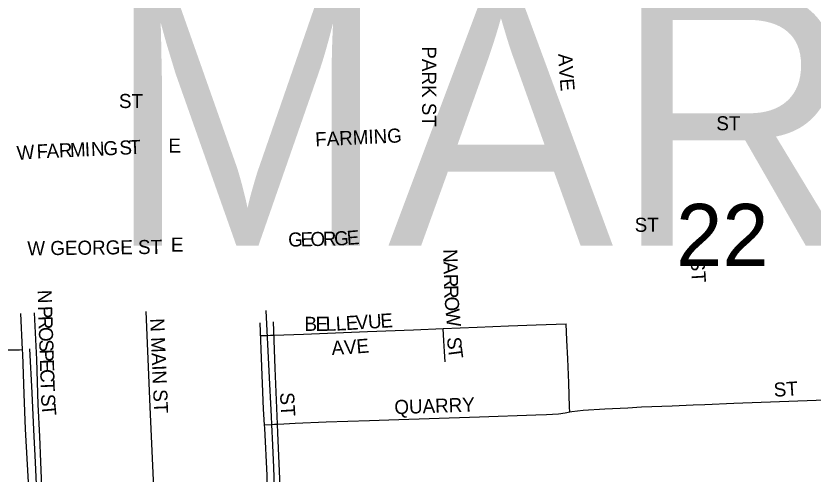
# Model space of a CAD drawing. Extents: x -97 to 34, y -21 to 22.
# Drawn here: x 5.626 to 6.163, y 19.796 to 20.104 of the extents above; entities that cross this region are included whole.
import ezdxf

# ---------------------------------------------------------------- set-up
doc = ezdxf.new("R2010")
doc.units = 0
for name, color, linetype in [('GM_X_City_Street', 7, 'Continuous'), ('GM_X_City_Street_Text', 7, 'Continuous'), ('GM_X_Section_Text', 7, 'Continuous'), ('GM_X_State_Route', 7, 'Continuous'), ('GM_X_Township_Text', 7, 'Continuous')]:
    doc.layers.add(name, color=color, linetype=linetype)

msp = doc.modelspace()

# ---------------------------------------------------------------- linework, layer by layer
at = {"layer": 'GM_X_City_Street'}
for points in [[(5.71984, 19.76387), (5.71944, 19.77089), (5.71848, 19.79156), (5.71627, 19.84134), (5.71468, 19.87863), (5.7134, 19.90538)], [(5.63016, 19.87977), (5.62911, 19.90401)], [(5.64434, 19.76026), (5.64409, 19.76775), (5.64386, 19.77424), (5.64327, 19.7874), (5.64248, 19.8043), (5.64189, 19.82119), (5.64071, 19.84279), (5.63971, 19.87305), (5.63831, 19.90448)], [(5.79319, 19.82924), (5.79254, 19.83969), (5.79188, 19.8569), (5.79136, 19.86817), (5.79023, 19.8978)], [(5.80206, 19.82962), (5.8005, 19.86723), (5.79928, 19.89839)], [(5.91361, 19.89391), (5.93649, 19.89484), (5.95767, 19.89576), (5.97635, 19.89642), (5.9964, 19.89703)], [(5.99896, 19.83792), (5.99883, 19.84113), (5.99817, 19.85731), (5.99751, 19.87365), (5.99698, 19.88606), (5.9964, 19.89703)], [(5.79049, 19.88927), (5.79149, 19.88929), (5.79523, 19.88937), (5.79717, 19.88941), (5.79963, 19.88945)], [(5.79963, 19.88945), (5.81951, 19.89027), (5.84106, 19.89102), (5.86264, 19.89191), (5.89361, 19.89312), (5.91361, 19.89391)], [(5.91489, 19.87165), (5.91449, 19.87861), (5.91409, 19.88573), (5.91361, 19.89391)], [(5.59927, 19.87888), (5.60538, 19.8789), (5.6114, 19.87911), (5.61433, 19.87928), (5.62046, 19.87952), (5.62812, 19.87972), (5.63016, 19.87977)], [(5.63571, 19.75992), (5.63503, 19.77443), (5.63345, 19.80233), (5.63226, 19.82629), (5.63127, 19.85006), (5.63029, 19.87677), (5.63016, 19.87977)], [(6.08195, 19.8426), (6.08996, 19.84293), (6.10955, 19.84383), (6.16498, 19.84575), (6.16898, 19.8459)], [(5.99896, 19.83792), (6.00019, 19.83816), (6.00792, 19.83904), (6.02246, 19.83994), (6.03802, 19.84057), (6.04734, 19.84121), (6.06782, 19.84204), (6.08195, 19.8426)], [(5.80206, 19.82962), (5.80623, 19.82985), (5.81379, 19.83021), (5.83487, 19.8311), (5.8639, 19.832), (5.87704, 19.83251), (5.93818, 19.83463), (5.9761, 19.83584), (5.98315, 19.83605), (5.99123, 19.83658), (5.99579, 19.83728), (5.99896, 19.83792)], [(5.79319, 19.82924), (5.79809, 19.82947), (5.79996, 19.82956), (5.80206, 19.82962)], [(5.79599, 19.76644), (5.7957, 19.77526), (5.79511, 19.78685), (5.79491, 19.7951), (5.79333, 19.82692), (5.79319, 19.82924)], [(5.80474, 19.76668), (5.80433, 19.77702), (5.80296, 19.8082), (5.80228, 19.82381), (5.80206, 19.82962)]]:
    msp.add_lwpolyline(points, dxfattribs=at)
at = {"layer": 'GM_X_State_Route'}
for points in [[(5.80294, 19.71473), (5.8016, 19.74704), (5.8008, 19.76569), (5.80077, 19.76657), (5.80019, 19.78098), (5.79942, 19.80041), (5.79882, 19.81541), (5.79809, 19.82947), (5.79783, 19.83465), (5.79637, 19.86532), (5.79443, 19.90607)], [(5.63488, 19.88036), (5.63635, 19.85068), (5.63754, 19.82581), (5.63863, 19.80411), (5.63934, 19.78901), (5.64023, 19.76731), (5.64048, 19.76193), (5.64055, 19.76011), (5.64121, 19.74363), (5.64237, 19.71146), (5.64311, 19.69074), (5.64379, 19.66695)]]:
    msp.add_lwpolyline(points, dxfattribs=at)

# ---------------------------------------------------------------- texts
at = {"layer": 'GM_X_City_Street_Text'}
for s, height, rotation, p in [('PARK ST', 0.00947, 270, (5.89944, 20.08394)), ('A', 0.00947, 272.9737, (5.99111, 20.07881)), ('V', 0.00947, 274.4858, (5.99156, 20.07022)), ('E', 0.00947, 274.5939, (5.99221, 20.0619)), ('ST', 0.00947, 0, (5.69516, 20.04239)), ('ST', 0.00947, 0, (6.09766, 20.02739)), ('FARMING', 0.00947, 2.6823, (5.82758, 20.01656)), ('W', 0.00947, 4.3923, (5.62666, 20.00738)), ('F', 0.00947, 2.6782, (5.63989, 20.00836)), ('A', 0.00947, 2.6016, (5.64654, 20.00867)), ('R', 0.00947, 2.6061, (5.65487, 20.00905)), ('M', 0.00947, 2.6059, (5.66236, 20.00939)), ('I', 0.00947, 2.622, (5.67235, 20.00984)), ('N', 0.00947, 2.6016, (5.67651, 20.01003)), ('G', 0.00947, 2.6083, (5.68484, 20.01041)), ('S', 0.00947, 2.5964, (5.69566, 20.0109)), ('T', 0.00947, 2.6035, (5.70232, 20.01121)), ('E', 0.00947, 0, (5.72849, 20.01239)), ('ST', 0.00947, 0, (6.04266, 19.95906)), ('G', 0.00947, 1.3332, (5.80928, 19.94906)), ('E', 0.00947, 1.3113, (5.81762, 19.94925)), ('O', 0.00947, 1.3338, (5.82429, 19.94941)), ('R', 0.00947, 1.3113, (5.83262, 19.9496)), ('G', 0.00947, 2.541, (5.84034, 19.94978)), ('E', 0.00947, 4.5939, (5.84903, 19.95017)), ('W GEORGE ST', 0.0094697, 0.6219, (5.63346, 19.94323)), ('E', 0.00947, 0, (5.73016, 19.94572)), ('N', 0.00947, 271.4643, (5.91361, 19.94732)), ('A', 0.00947, 271.4643, (5.91382, 19.93899)), ('ST', 0.00947, 273.5738, (6.08027, 19.94072)), ('R', 0.00947, 271.457, (5.91403, 19.93066)), ('R', 0.00947, 271.7868, (5.91422, 19.9231)), ('N', 0.00947, 271.88, (5.64027, 19.91983)), ('O', 0.00947, 274.2248, (5.91448, 19.91516)), ('P', 0.00947, 271.8855, (5.64063, 19.909)), ('W', 0.00947, 275.1648, (5.91511, 19.90669)), ('R', 0.00947, 271.8703, (5.64085, 19.90234)), ('N MAIN ST', 0.00947, 272.4527, (5.71611, 19.90069)), ('B', 0.00947, 0.0486, (5.82016, 19.89239)), ('E', 0.00947, 0.0546, (5.82766, 19.8924)), ('L', 0.00947, 0.7567, (5.83445, 19.89241)), ('L', 0.00947, 3.0532, (5.84152, 19.89251)), ('E', 0.00947, 3.649, (5.84829, 19.89286)), ('V', 0.00947, 3.6527, (5.85494, 19.89329)), ('U', 0.00947, 3.6429, (5.86325, 19.89382)), ('E', 0.00947, 3.636, (5.87157, 19.89435)), ('O', 0.00947, 271.897, (5.64109, 19.89484)), ('S', 0.00947, 271.9022, (5.64137, 19.88651)), ('A', 0.00947, 3.0392, (5.83862, 19.8761)), ('V', 0.00947, 4.2472, (5.84716, 19.87656)), ('E', 0.00947, 4.3811, (5.8555, 19.87718)), ('S', 0.00947, 275.281, (5.91612, 19.88788)), ('P', 0.00947, 271.9022, (5.64159, 19.87985)), ('T', 0.00947, 277.4489, (5.91678, 19.88085)), ('E', 0.00947, 271.8855, (5.64181, 19.87318)), ('C', 0.00947, 271.8703, (5.64202, 19.86652)), ('T', 0.00947, 271.9022, (5.64227, 19.85902)), ('ST', 0.00947, 3.5746, (6.13663, 19.84797)), ('S', 0.00947, 272.6785, (5.64258, 19.84972)), ('ST', 0.00947, 273.5746, (5.8036, 19.85072)), ('QUARRY', 0.00947, 1.9442, (5.88088, 19.8363)), ('T', 0.00947, 275.0695, (5.64292, 19.84263))]:
    msp.add_text(s, height=height, rotation=rotation, dxfattribs=at).set_placement(p)
at = {"layer": 'GM_X_Section_Text'}
msp.add_text('22', height=0.041856, rotation=0, dxfattribs=at).set_placement((6.07058, 19.93598))
at = {"layer": 'GM_X_Township_Text'}
msp.add_text('CITY OF MARION', height=0.1704545, rotation=0, dxfattribs=at).set_placement((4.72404, 19.9498))

doc.saveas('drawing.dxf')
